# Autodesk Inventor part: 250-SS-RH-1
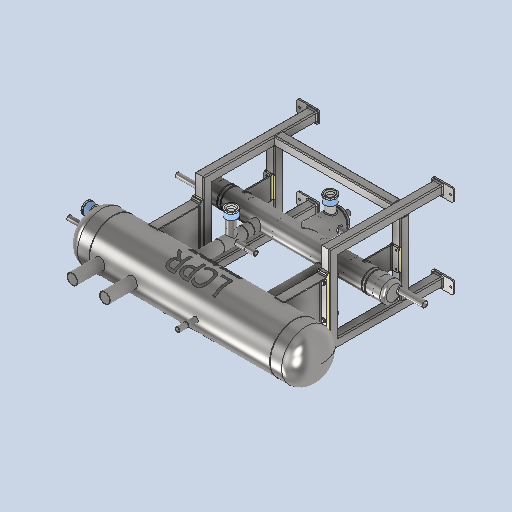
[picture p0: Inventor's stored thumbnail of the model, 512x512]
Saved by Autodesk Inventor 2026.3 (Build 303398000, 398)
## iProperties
Created: 2026-05
Part Number: 250-SS-RH-1
Material: Generic
Document SubType Name: Modeling
Designer: rva
Density: 1 g/cm^3
Appearance: Default
Author: rva
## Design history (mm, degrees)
derived "250-SS-RH.iam"
body "Solid1"
node "LCPR-SS-100- Sub Cooler-RH.iam:1::ISO 5251 Equal Tee DN100 3"
node "LCPR-SS-100- Sub Cooler-RH.iam:1::SS-100-14 hole Sub Cooler "
node "LCPR-SS-100- Sub Cooler-RH.iam:1::SS-100-14 hole Sub Cooler "
node "LCPR-SS-100- Sub Cooler-RH.iam:1::100 mm Subcooler Leg.ipt:1"
node "LCPR-SS-100- Sub Cooler-RH.iam:1::LCPR-SS-100 Blank Plate.ip"
node "LCPR-SS-100- Sub Cooler-RH.iam:1::100 mm Subcooler Leg.ipt:2"
node "LCPR-SS-100- Sub Cooler-RH.iam:1::1-2 Inch NPT Socket - SS.i"
node "LCPR-SS-100- Sub Cooler-RH.iam:1::H1100-R.ipt:1"
node "LCPR-SS-100- Sub Cooler-RH.iam:1::H1100-R.ipt:2"
node "LCPR-SS-100- Sub Cooler-RH.iam:1::1-2 Inch NPT Socket - SS.i"
node "LCPR-SS-100- Sub Cooler-RH.iam:1::1-2 Inch NPT Socket - SS.i"
node "LCPR-SS-100- Sub Cooler-RH.iam:1::Welds"
node "LCPR-SS-250-Frame Assembly.iam:2::LCPR-SS-250-120 x 70 Frame"
node "LCPR-SS-250-Frame Assembly.iam:2::LCPR-SS-250-120 x 70 Frame"
node "LCPR-SS-250-Frame Assembly.iam:2::LCPR-SS-250-120 x 70 Frame"
node "LCPR-SS-250-Frame Assembly.iam:2::LCPR-SS-250-120 x 70 Frame"
node "LCPR-SS-250-Frame Assembly.iam:2::Welds"
node "Nylon Heat Tranfer Spacer 276.5x50.ipt:1"
node "Nylon Heat Tranfer Spacer 276.5x50.ipt:2"
node "AS 1111 - Metric M10 x 80:1"
node "AS 1112 (4) - Metric M10:1"
node "AS 1237 (4.1) 10 mm:1"
node "AS 1237 (4.1) 10 mm:2"
node "AS 1111 - Metric M10 x 80:2"
node "AS 1112 (4) - Metric M10:2"
node "AS 1237 (4.1) 10 mm:3"
node "AS 1237 (4.1) 10 mm:4"
node "AS 1111 - Metric M10 x 80:3"
node "AS 1112 (4) - Metric M10:3"
node "AS 1237 (4.1) 10 mm:5"
node "AS 1237 (4.1) 10 mm:6"
node "AS 1111 - Metric M10 x 80:4"
node "AS 1112 (4) - Metric M10:4"
node "AS 1237 (4.1) 10 mm:7"
node "AS 1237 (4.1) 10 mm:8"
node "250-SS-SHELL-WELD.iam:1::ASME B36.10M Pipe 10.75 x 0.165 - 3"
node "250-SS-SHELL-WELD.iam:1::LCPR-LOGO.ipt:1"
node "250-SS-SHELL-WELD.iam:1::LCPR-SS-250 mm Dome End Cap.ipt:1"
node "250-SS-SHELL-WELD.iam:1::ANSI/ASME B36.19M Pipe 2 - Schedule"
node "250-SS-SHELL-WELD.iam:1::H1100-R.ipt:1"
node "250-SS-SHELL-WELD.iam:1::LCPR-SS-250-Leg Assembly.iam:1::Wel"
node "250-SS-SHELL-WELD.iam:1::LCPR-SS-250-Leg Assembly.iam:2::Wel"
node "250-SS-SHELL-WELD.iam:1::LCPR-SS-250 mm Dome End Cap.ipt:2"
node "Nylon Heat Tranfer Spacer 120x50.ipt:1"
node "Nylon Heat Tranfer Spacer 120x50.ipt:2"
node "250-SS-RH.iam_Bodies"
